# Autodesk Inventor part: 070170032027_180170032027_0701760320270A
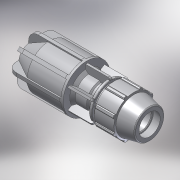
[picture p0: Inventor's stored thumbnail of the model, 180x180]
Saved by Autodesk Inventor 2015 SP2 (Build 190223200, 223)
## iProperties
Created: 2017-02
Part Number: 070170032027_180170032027_0701760320270A
Material: PVC-Piping
Description: PLASSON PLASS4 COUPLING 20-27*32
Document SubType Name: Modeling
Designer: KIM
Mass: 92.6774 g
Surface Area: 199.44 cm^2
Volume: 66.1981 cm^3
Density: 1.4 g/cm^3
Appearance: Smooth - White
Author: KIM
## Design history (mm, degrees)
derived "070170.ipt"
feature "Solid1::070170.ipt"
tag "TaggingFeature1"
body "Solid1"
other parameters: "d2" = 32, "d4" = 12.85714, "d5" = 23.45, "d7" = 64, "d8" = 38.84092, "d9" = 11.57143, "d11" = 4.5, "d12" = 51.2, "d13" = 120 deg, "d14" = 44.8, "d15" = 12 deg, "d16" = 57.6, "d18" = 1.6, "d19" = 35 deg, "d20" = 17.5 deg, "d21" = 59.52, "d23" = 0, "d25" = 360 deg, "d27" = 1.28, "d42" = 30.15, "d43" = 1.92, "d46" = 0.96, "d53" = 0.64, "d67" = 3.2, "d70" = 28.8, "d71" = 67, "d74" = 180 deg, "d75" = 27, "d76" = 71, "d80" = 28.8, "d84" = 67.45, "d85" = 135 deg, "d86" = 3.55, "d89" = 3.55, "d90" = 135 deg, "d94" = 3.55, "d97" = 5.12, "d98" = 0, "d100" = 360 deg, "d102" = 78.1, "d103" = 14.2, "d104" = 5.68, "d105" = 0, "d110" = 85, "d112" = 108, "d113" = 28.9, "d114" = 72, "d115" = 42.6, "d116" = 108, "d117" = 4.25, "d118" = 32, "d119" = 3.2, "d120" = 0, "d121" = 3.2, "d123" = 360 deg, "d_" = 32, "E_" = 64, "A_" = 81, "l_" = 67, "d_1" = 27, "E_1" = 71, "l_1" = 85, "d106" = 38.84092
